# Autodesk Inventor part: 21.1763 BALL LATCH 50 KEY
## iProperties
Created: 2007-03
Part Number: 21.1763 BALL LATCH 50 KEY
Document SubType Name: Modeling
Designer: Andy Moles
Material: Steel
Density: 7.85 g/cm^3
Author: Andy Moles
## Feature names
1. Extrusion1
2. Extrusion2
3. Chamfer1
4. Chamfer2
